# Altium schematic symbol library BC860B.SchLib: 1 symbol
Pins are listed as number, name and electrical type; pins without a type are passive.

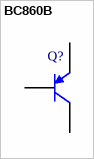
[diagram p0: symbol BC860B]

## BC860B
designator Q?
PNP Silicon AF Transistor, 45 V VCEO, 100 mA IC, SOT23, Reel, Green; Manufacturer: Infineon; PartNumber: BC860B; fT (typ): 250 MHz; Green: TRUE; IC: 2 mA; IC (max): 100 mA; ICBO (max): 15nA; ICM (max): 200 mA; VCBO (max): 50 V; VCE: 5 V; VCEO (max): 45 V; VEBO (max): 5 V
footprint INF-SOT23_N (SOT23, 3-Leads, Body 2.9x1.3 mm, Pitch 0.95 mm, IPC Medium Density)
footprint INF-SOT23_L (SOT23, 3-Leads, Body 2.9x1.3 mm, Pitch 0.95 mm, IPC High Density)
footprint INF-SOT23_M (SOT23, 3-Leads, Body 2.9x1.3 mm, Pitch 0.95 mm, IPC Low Density)
pins: 1 B, 2 E, 3 C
